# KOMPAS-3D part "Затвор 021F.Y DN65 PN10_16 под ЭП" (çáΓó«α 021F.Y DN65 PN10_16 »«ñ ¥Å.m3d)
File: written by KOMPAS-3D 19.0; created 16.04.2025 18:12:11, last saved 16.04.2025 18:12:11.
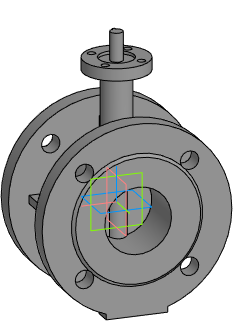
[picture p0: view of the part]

Document properties: Автор: Евгений; Полное имя файла: E:\Dendor Работа Сачек\3D для проекитирвщиков\1.6 Тип 021F.Y Затвор дисковый поворотный фланцевый\stp_Тип 021F.Y Затвор  DN40 PN10_16 под ЭП\Затвор 021F.Y DN65 PN10_16 под ЭП.m3d

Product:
- Part/product: Затвор 021F.Y DN65 PN10_16 под ЭП

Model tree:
1. Операция без истории:1  (labels: Затвор 021F.Y DN65 PN10_16 под ЭП)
